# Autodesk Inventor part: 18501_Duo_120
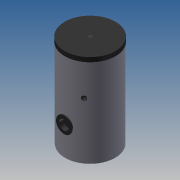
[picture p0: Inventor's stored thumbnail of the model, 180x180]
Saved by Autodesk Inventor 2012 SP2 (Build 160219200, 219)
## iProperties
allow_slope_adjustment: 0 ul
connection_type: 13 ul
flow_configuration2: 1 ul
flow_direction: 2 ul
loss_method: 0 ul
radius: 16,625 mm
radius: 9,500 mm
radius: 15,375 mm
Created: 2014-05
Part Number: 18501_Duo_120
Material: Default
Document SubType Name: Modeling
Designer: michel
Density: 1 g/cm^3
description: 0:0:18500_Duo_120
manufacturer: 0:0:Flamco Group
model: 0:0:Duo 120
url: 0:0:www.flamcogroup.com
radius: 22,625 mm
radius: 19,625 mm
Author: michel
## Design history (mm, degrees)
sketch "Sketch1"
  geometry: C1 r 280 at (0, 0); 1 further point
  constraints: 1 centre point, 1 coincident
  dimensions: "d0" = 560 diameter of C1
extrude "Extrusion1" new body sketch "Sketch1" distance "d1" = 1040; taper "d2" = 0 deg
sketch "Sketch2"
  geometry: L1 (-280, 1040)-(280, 1040) reference; L2 (280, 0)-(280, 1040) reference; L3 (280, 1040)-(280, 990); L4 (285, 990)-(285, 1040); L5 (285, 1040)-(280, 1040); L6 (0, -208)-(0, 1248) reference; L7 (285, 990)-(280, 990); 1 further point
  constraints: 8 end point, 1 parallel
revolve "Revolution1" sketch "Sketch2" stored, may be unused: angle "d6" = 90 deg
workplane "Work Plane1"
workplane "Work Plane2"
workplane "Work Plane3"
workplane "Work Plane4"
workplane "Work Plane5"
workplane "Work Plane6"
sketch "Sketch3"
  geometry: L1 (399, 885)-(-399, 885) reference; L2 (399, 635)-(-399, 635) reference; L3 (399, 545)-(-399, 545) reference; L4 (399, 245)-(-399, 245) reference; L5 (399, 65)-(-399, 65) reference; L6 (280, 0)-(280, 990) reference; L7 (290, 885)-(240, 885); L8 (240, 885)-(240, 901.625); L9 (240, 901.625)-(290, 901.625); L10 (290, 901.625)-(290, 885); L11 (290, 65)-(240, 65); L12 (240, 65)-(240, 81.625); L13 (240, 81.625)-(290, 81.625); L14 (290, 81.625)-(290, 65); L15 (280, 635)-(240, 635); L16 (240, 635)-(240, 645.475); L17 (240, 645.475)-(280, 645.475); L18 (280, 645.475)-(280, 635); L19 (280, 545)-(240, 545); L20 (240, 545)-(240, 561.625); L21 (240, 561.625)-(280, 561.625); L22 (280, 561.625)-(280, 545); L23 (240, 261.625)-(280, 261.625); L24 (280, 261.625)-(280, 245); L25 (280, 245)-(240, 245); L26 (240, 245)-(240, 261.625); 1 further point
  constraints: 40 end point, 8 parallel, 4 point on line, 3 horizontal, 3 perpendicular
  dimensions: "d13" = 50 distance of L8.end L9.end; "d14" = 16.625 distance of L7.end L8.end; "d15" = 50 distance of L12.end L13.end; "d16" = 16.625 distance of L11.end L12.end; "d17" = 40 distance of L16.end L17.end; "d18" = 10.475 distance of L15.end L16.end; "d19" = 40 distance of L20.end L21.end; "d20" = 16.625 distance of L19.end L20.end; "d21" = 40 distance of L23.start L23.end; "d22" = 16.625 distance of L25.end L23.start
revolve "Revolution2" stored, may be unused: angle "d23" = 90 deg
revolve "Revolution3" stored, may be unused: angle "d24" = 90 deg
revolve "Revolution4" stored, may be unused: angle "d25" = 90 deg
revolve "Revolution5" stored, may be unused: angle "d26" = 90 deg
revolve "Revolution6" stored, may be unused: angle "d27" = 90 deg
revolve "Revolution7" stored, may be unused: angle "d28" = 90 deg
revolve "Revolution8" stored, may be unused: angle "d29" = 90 deg
sketch "Sketch4"
  geometry: C1 r 16.625 at (0, 0) reference; C2 r 15.375 at (0, 0); 1 further point
  constraints: 1 centre point, 1 coincident
  dimensions: "d30" = 30.75 diameter of C2
extrude "Extrusion2" cut sketch "Sketch4" distance "d31" = 40; taper "d32" = 0 deg
sketch "Sketch5"
  geometry: C1 r 16.625 at (0, 0) reference; C2 r 15.375 at (0, 0); 1 further point
  constraints: 1 centre point, 1 coincident
  dimensions: "d33" = 30.75 diameter of C2
extrude "Extrusion3" cut sketch "Sketch5" distance "d34" = 40; taper "d35" = 0 deg
workplane "Work Plane7"
sketch "Sketch6"
  geometry: C1 r 9.5 at (0, 0); C2 r 16.625 at (0, -90) reference; C3 r 16.625 at (0, -390) reference; C4 r 15.375 at (0, -90); C5 r 15.375 at (0, -390); 7 further points
  constraints: 6 vertical alignment, 3 centre point, 2 coincident
  dimensions: "d36" = 19 diameter of C1; "d37" = 30.75 diameter of C4; "d38" = 30.75 diameter of C5
  node "Projected Loop1"
  node "Projected Loop2"
extrude "Extrusion4" join sketch "Sketch6" distance "d39" = 40; taper "d40" = 0 deg
extrude "Extrusion5" join sketch "Sketch6" distance "d41" = 40; taper "d42" = 0 deg
extrude "Extrusion6" join sketch "Sketch6" distance "d43" = 40; taper "d44" = 0 deg
workplane "Work Plane8"
workplane "Work Plane9"
sketch "Sketch7"
  geometry: L1 (405, 327)-(-400, 327) reference; L2 (-280, 0)-(-280, 990) reference; L3 (-280, 327)-(-292.5, 327); L4 (-292.5, 327)-(-292.5, 417); L5 (-292.5, 417)-(-280, 417); L6 (-280, 417)-(-280, 327); 1 further point
  constraints: 8 end point, 2 parallel, 2 point on line, 1 horizontal, 1 perpendicular
  dimensions: "d47" = 12.5 distance of L4.end L5.end; "d48" = 90 distance of L3.end L4.end
revolve "Revolution9" sketch "Sketch7" stored, may be unused: angle "d49" = 90 deg
sketch "Sketch8"
  geometry: C1 r 62.5 at (0, 0); A1 r 90 centre (0, 0) between (0, -90) and (0, 90) reference; 1 further point
  constraints: 1 centre point, 1 coincident
  dimensions: "d50" = 125 diameter of C1
extrude "Extrusion7" join sketch "Sketch8" stored distance "d51" = 10; taper "d52" = 0 deg
sketch "Sketch9"
  geometry: C1 r 90 at (0, 0) reference; C2 r 55 at (0, 0); 1 further point
  constraints: 1 centre point, 1 coincident
  dimensions: "d53" = 110 diameter of C2
extrude "Extrusion8" cut sketch "Sketch9" distance "d54" = 50; taper "d55" = 0 deg
sketch "Sketch10"
  geometry: C1 r 285 at (0, 0) reference; C2 r 20.955 at (0, 0); C3 r 19.625 at (0, 0)
  constraints: 2 centre point, 2 coincident
  dimensions: "d56" = 41.91 diameter of C2; "d59" = 39.25 diameter of C3
extrude "Extrusion9" cut sketch "Sketch10" distance "d57" = 50; taper "d58" = 0 deg
extrude "Extrusion10" join sketch "Sketch10" distance "d60" = 50; taper "d61" = 0 deg
workplane "Work Plane10"
sketch "Sketch11"
  geometry: L1 (635, -561.842)-(635, 563.89) reference; L2 (0, 280)-(990, 280) reference; L3 (635, 280)-(658.9, 280); L4 (658.9, 280)-(658.9, 240); L5 (658.9, 240)-(635, 240); L6 (635, 240)-(635, 280); L7 (612.375, 240)-(612.375, 280); L8 (612.375, 240)-(609.825, 240); L9 (609.825, 240)-(609.825, 280); L10 (612.375, 280)-(609.825, 280); 1 further point
  constraints: 16 end point, 4 perpendicular, 4 point on line, 2 parallel, 1 horizontal
  dimensions: "d63" = 23.9 distance of L4.end L5.end; "d64" = 40 distance of L3.end L4.end; "d67" = 22.625 distance of L5.end L7.start; "d68" = 2.55 distance of L7.start L8.end
revolve "Revolution10" stored, may be unused: angle "d65" = 90 deg
revolve "Revolution11" stored, may be unused: angle "d69" = 90 deg
body "Solid1"
other parameters: "d7" = -885, "d8" = -65, "d9" = -245, "d10" = -545, "d11" = -635, "d12" = 0, "d45" = -327, "d46" = 0, "d62" = 35 deg
